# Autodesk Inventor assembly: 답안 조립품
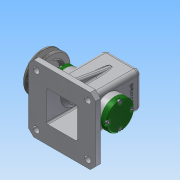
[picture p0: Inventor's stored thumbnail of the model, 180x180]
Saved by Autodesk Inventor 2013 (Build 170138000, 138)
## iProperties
Created: 2016-02
Part Number: 답안 조립품
Document SubType Name: Assembly
Designer: Administrator
Author: Administrator
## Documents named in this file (16)
- C:\Users\Administrator\Desktop\460212V1024\답안 조립품.iam
- C:\Users\Administrator\Desktop\460212V1024\본체.ipt
- C:\Users\Administrator\Desktop\460212V1024\V벨트풀리.ipt
- C:\Users\Administrator\Desktop\460212V1024\고정핀 1.2 x 10.ipt
- C:\Users\Administrator\Desktop\460212V1024\뒤커버.ipt
- C:\Users\Administrator\Desktop\460212V1024\링크.ipt
- C:\Users\Administrator\Desktop\460212V1024\멈춤나사 M3x8.ipt
- C:\Users\Administrator\Desktop\460212V1024\베어링 12 x 32 x 10.ipt
- C:\Users\Administrator\Desktop\460212V1024\볼트 M4 x 12.ipt
- C:\Users\Administrator\Desktop\460212V1024\부시.ipt
- C:\Users\Administrator\Desktop\460212V1024\슬라이드.ipt
- C:\Users\Administrator\Desktop\460212V1024\앞커버.ipt
- C:\Users\Administrator\Desktop\460212V1024\오일실 12 25 7.ipt
- C:\Users\Administrator\Desktop\460212V1024\키 4 x 4 x 10.ipt
- C:\Users\Administrator\Desktop\460212V1024\편심축.ipt
- C:\Users\Administrator\Desktop\460212V1024\핀 5 x 18.ipt
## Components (11 placed, 4 different names)
1. V벨트풀리:1
2. 고정핀 1.2 x 10:1
3. 핀 5 x 18:1
4. ISO 4762 M4 x 12:1
5. ISO 4762 M4 x 12:3
6. ISO 4762 M4 x 12:4
7. ISO 4762 M4 x 12:5
8. ISO 4762 M4 x 12:2
9. ISO 4762 M4 x 12:6
10. ISO 4762 M4 x 12:7
11. ISO 4762 M4 x 12:8
